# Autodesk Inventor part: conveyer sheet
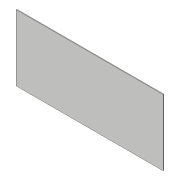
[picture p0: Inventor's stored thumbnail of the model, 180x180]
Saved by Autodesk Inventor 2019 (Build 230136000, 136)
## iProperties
Created: 2019-10
Part Number: conveyer sheet
Material: Generic
Document SubType Name: Sheet Metal
Designer: hp
Density: 1 g/cm^3
Sheet Metal Rule: Default_mm
Appearance: Default
Author: hp
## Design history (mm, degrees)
node "Face1"
  sketch "Sketch1"
    geometry: L1 (-116.883, 114.128)-(283.117, 114.128); L2 (283.117, 114.128)-(283.117, -65.872); L3 (283.117, -65.872)-(-116.883, -65.872); L4 (-116.883, -65.872)-(-116.883, 114.128); 1 further point
    constraints: 8 end point, 2 parallel, 1 horizontal, 1 perpendicular
    dimensions: "d3" = 400 distance of L2.end L3.end; "d4" = 180 distance of L1.end L2.end
body "Solid1"
face "Plate1" dims "d2" = 2 (= Thickness)
other parameters: "Thickness" = 2 (derived), "BendRadius" = 2 (= Thickness), "BendReliefWidth" = 2 (= Thickness), "BendReliefDepth" = 1 (= 0.5 x Thickness), "CornerReliefSize" = 8 (= 4 x Thickness), "SeamGap" = 0.01, "MinimumRemnant" = 4 (= 2 x Thickness), "TransitionRadius" = 2 (= BendRadius), "JacobiRadiusSize" = 2 (= BendRadius), "GapSize" = 2 (= Thickness)
